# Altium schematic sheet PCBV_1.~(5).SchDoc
size A4; SheetNumber: 1; SheetTotal: 1
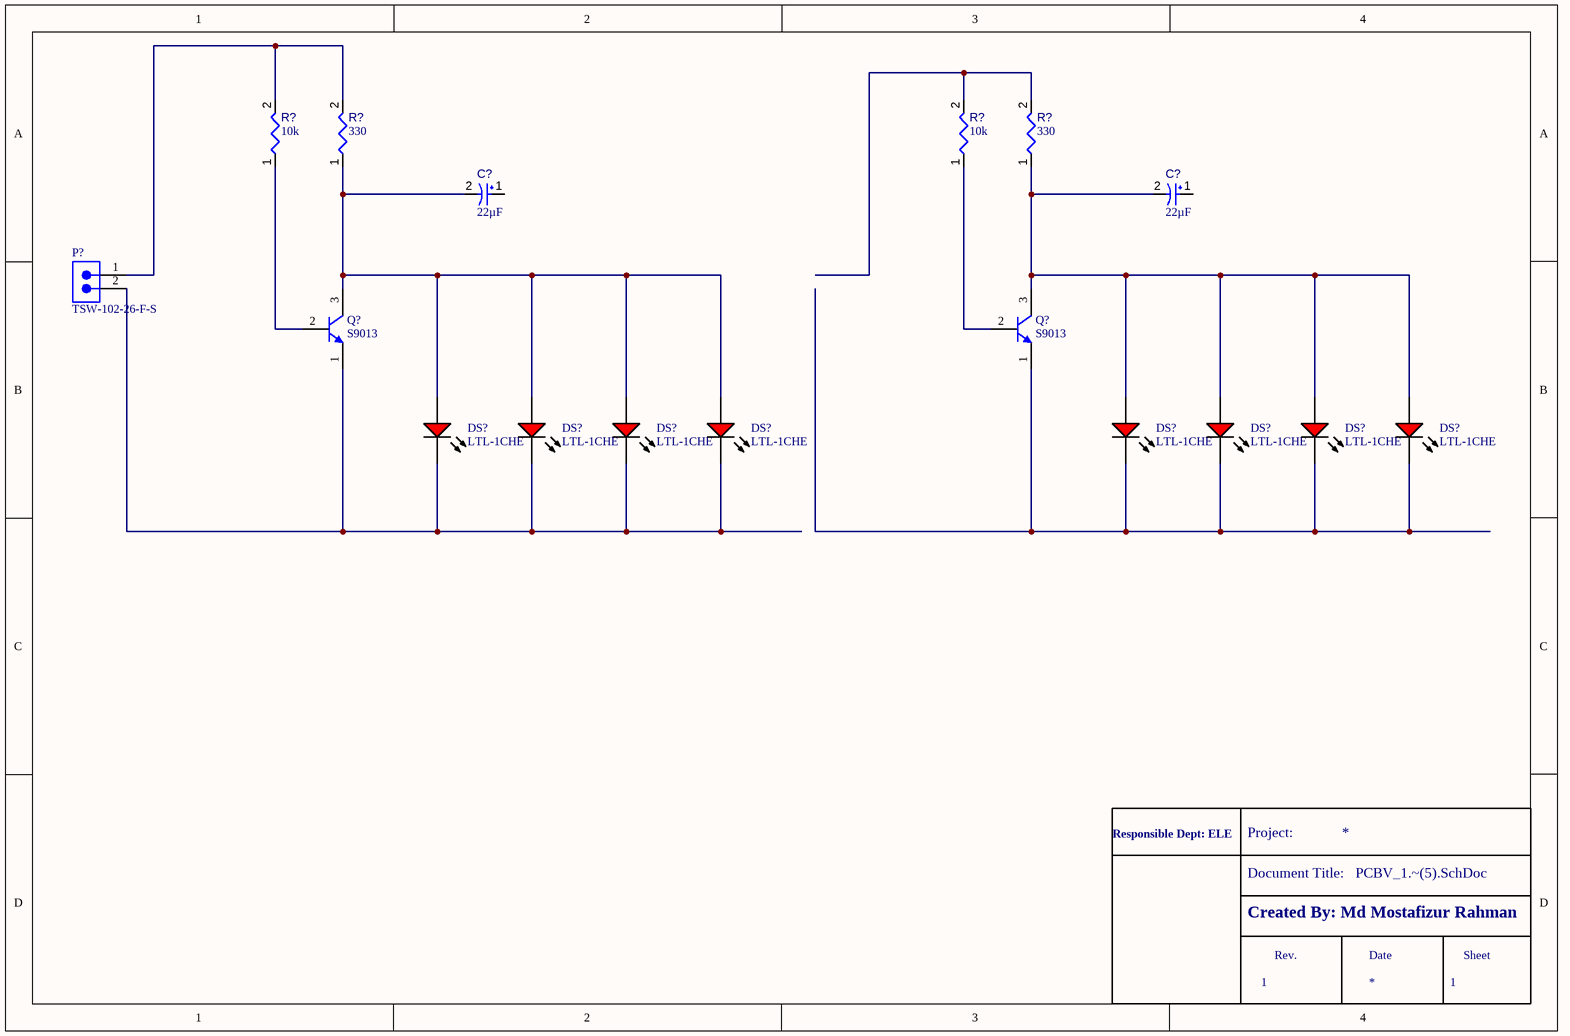
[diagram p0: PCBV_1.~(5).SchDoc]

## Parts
(Parts that share a designator on the sheet are numbered #1, #2 ... from top to bottom, then left to right.)
*  HSHL Title Block  (value not drawn)  (graphical)
C?#1  value 22µF  [CAPPR55-200-1100X500X1200]  (hidden comment: ECA1HM220)
C?#2  value 22µF  [CAPPR55-200-1100X500X1200]  (hidden comment: ECA1HM220)
DS?#1  LTL-1CHE  [INDPR60-254-520X380X650]
DS?#2  LTL-1CHE  [INDPR60-254-520X380X650]
DS?#3  LTL-1CHE  [INDPR60-254-520X380X650]
DS?#4  LTL-1CHE  [INDPR60-254-520X380X650]
DS?#5  LTL-1CHE  [INDPR60-254-520X380X650]
DS?#6  LTL-1CHE  [INDPR60-254-520X380X650]
DS?#7  LTL-1CHE  [INDPR60-254-520X380X650]
DS?#8  LTL-1CHE  [INDPR60-254-520X380X650]
P?  TSW-102-26-F-S  [SMTC-TSW-102-26-XX-S]
Q?#1  S9013  [JSCJ-TO-92-3_V]
Q?#2  S9013  [JSCJ-TO-92-3_V]
R?#1  value 10k  [RESA60-630X240]  (hidden comment: MFR-25FBF52-10K)
R?#2  value 330  (hidden comment: CF18JT330R)
R?#3  value 10k  [RESA60-630X240]  (hidden comment: MFR-25FBF52-10K)
R?#4  value 330  (hidden comment: CF18JT330R)

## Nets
NetC?#1_2: C?#1.2 DS?#1.1(A) DS?#2.1(A) DS?#3.1(A) DS?#4.1(A) Q?#1.3(C) R?#2.1
NetC?#2_2: C?#2.2 DS?#5.1(A) DS?#6.1(A) DS?#7.1(A) DS?#8.1(A) Q?#2.3(C) R?#4.1
NetDS?#1_2: DS?#1.2(K) DS?#2.2(K) DS?#3.2(K) DS?#4.2(K) P?.2 Q?#1.1(E)
NetDS?#5_2: DS?#5.2(K) DS?#6.2(K) DS?#7.2(K) DS?#8.2(K) Q?#2.1(E)
NetP?_1: P?.1 R?#1.2 R?#2.2
NetQ?#1_2: Q?#1.2(B) R?#1.1
NetQ?#2_2: Q?#2.2(B) R?#3.1
NetR?#3_2: R?#3.2 R?#4.2

Not connected (* = marked no-connect by the designer): C?#1 1; C?#2 1

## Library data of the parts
C?#1 C?#2 = CMP-001-00027-7: Aluminum Electrolytic Capacitor, 22 uF, +/- 20%, 50 V, -40 to 85 degC, 2-Pin THD, RoHS, Bulk; Manufacturer: Panasonic; Ripple Current (AC): 100mA; Voltage Rating: 50V
DS?#1-DS?#8 = CMP-007-00018-2: LED Uni-Color Red, 100 mW, 30 mA, -55 to 100 degC, 2-Pin THD, RoHS, Bulk; Manufacturer: Lite-On; Forward Current: 20mA; Nominal Vf: 2V; Viewing Angle: 60degrees; Luminous Intensity: 12.6mcd; Lens Style: Dome
P? = CMP-1024-00329-1: 0.025" SQ Post Header, Through-hole, Vertical, -55 to 125 degC, 2.54 mm Pitch, 2-Pin, Male, RoHS; Manufacturer: Samtec; Pitch: 2.54 mm
Q?#1 Q?#2 = CMP-013-00000-3: Transistor, NPN, 0.1 uA, 150 MHz, 3-Pin TO-92; Manufacturer: Jiangsu Changjiang Electronics Technology
R?#1 R?#3 = CMP-009-00047-4: Axial Resistor, 10 KOhm, +/- 1%, 0.25 W, -55 to 155 degC, 2-Pin THD, RoHS, Bulk; Manufacturer: Yageo; Power: 250mW; Voltage Rating: 250V
R?#2 R?#4 = CMP-009-00177-1: Fixed Resistor, Carbon Film, 0.125W, 330ohm, 250V, 5% +/-Tol, -400, 0ppm/Cel, Through Hole Mount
